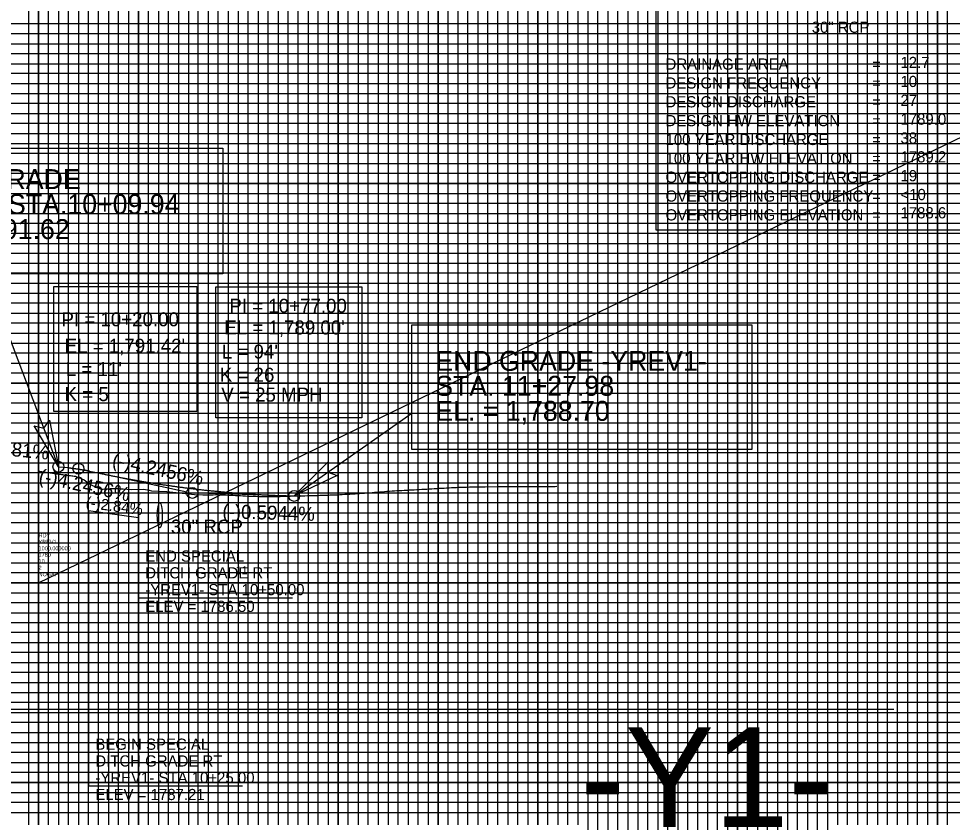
# Model space of a CAD drawing. Extents: x 572269 to 579912, y -56875 to -49627.
# Drawn here: x 574574.7 to 575042.2, y -53465.2 to -53065.2 of the extents above; entities that cross this region are included whole.
import ezdxf

# ---------------------------------------------------------------- set-up
doc = ezdxf.new("R2010")
doc.units = 0
for name, color, linetype in [('Default', 7, 'Continuous'), ('Exist Profile Cell', 7, 'Continuous'), ('Exist Vertical Profile Ground Line', 7, 'Continuous'), ('Prop Grid Mask', 7, 'Continuous'), ('Prop PFL Structure Hydraulic Data Label CELL', 7, 'Continuous'), ('Prop PFL Text', 7, 'Continuous'), ('Prop Vertical Profile Ditch Grade Right', 7, 'Continuous'), ('Prop Vertical Profile Ditch Grade Right Label', 7, 'Continuous'), ('Prop Vertical Profile Grade', 7, 'Continuous'), ('Prop Vertical Profile Grade Label', 7, 'Continuous'), ('Prop VPI Label', 7, 'Continuous'), ('Scratch_Level_0', 7, 'Continuous'), ('Scratch_Level_3', 7, 'Continuous'), ('Scratch_Level_5', 7, 'Continuous'), ('Scratch_Level_6', 7, 'Continuous'), ('Sheet Cutting Line CELL', 7, 'Continuous'), ('Sheet DOT Grid CELL', 7, 'Continuous'), ('Sheet Profile Grid Major CELL', 7, 'Continuous'), ('Sheet Profile Grid Middle CELL', 7, 'Continuous'), ('Sheet Profile Grid Minor CELL', 7, 'Continuous'), ('Typical Terminator CELL', 7, 'Continuous')]:
    doc.layers.add(name, color=color, linetype=linetype)

# ---------------------------------------------------------------- blocks, each defined once
blk = doc.blocks.new('TERMINATOR')
at = {"layer": 'Typical Terminator CELL'}
blk.add_lwpolyline([(-0.4687, 0.0807), (0, 0), (-0.4713, -0.0833), (-0.4114, 0)], close=True, dxfattribs=at)
blk = doc.blocks.new('PROFILE SHEET SINGLE')
at = {"layer": 'Sheet DOT Grid CELL'}
for p, q in [((15, 21), (15, 0.5)), ((16, 21), (16, 0.5)), ((17, 21), (17, 0.5)), ((18, 21), (18, 0.5)), ((19, 21), (19, 0.5)), ((20, 21), (20, 0.5)), ((21, 21), (21, 0.5)), ((22, 21), (22, 0.5)), ((23, 21), (23, 0.5)), ((24, 21), (24, 0.5)), ((0, 14.5), (30, 14.5)), ((0, 13.5), (30, 13.5)), ((0, 12.5), (30, 12.5)), ((0, 11.5), (30, 11.5)), ((0, 10.5), (30, 10.5)), ((0, 9.5), (30, 9.5)), ((0, 8.5), (30, 8.5)), ((0, 7.5), (30, 7.5))]:
    blk.add_line(p, q, dxfattribs=at)
at = {"layer": 'Sheet Profile Grid Major CELL'}
for points in [[(15, 21), (15, 0.5), (16, 0.5), (16, 21)], [(17, 21), (17, 0.5), (18, 0.5), (18, 21)], [(19, 21), (19, 0.5), (20, 0.5), (20, 21)], [(21, 21), (21, 0.5), (22, 0.5), (22, 21)], [(23, 21), (23, 0.5), (24, 0.5), (24, 21)], [(30, 13.5), (0, 13.5), (0, 14.5), (30, 14.5)], [(30, 11.5), (0, 11.5), (0, 12.5), (30, 12.5)], [(30, 9.5), (0, 9.5), (0, 10.5), (30, 10.5)], [(30, 7.5), (0, 7.5), (0, 8.5), (30, 8.5)]]:
    blk.add_lwpolyline(points, dxfattribs=at)
at = {"layer": 'Sheet Profile Grid Middle CELL'}
for points in [[(14.5, 21), (14.5, 0.5), (15.5, 0.5), (15.5, 21)], [(16.5, 21), (16.5, 0.5), (17.5, 0.5), (17.5, 21)], [(18.5, 21), (18.5, 0.5), (19.5, 0.5), (19.5, 21)], [(20.5, 21), (20.5, 0.5), (21.5, 0.5), (21.5, 21)], [(22.5, 21), (22.5, 0.5), (23.5, 0.5), (23.5, 21)], [(30, 15), (0, 15), (0, 14), (30, 14)], [(30, 13), (0, 13), (0, 12), (30, 12)], [(30, 11), (0, 11), (0, 10), (30, 10)], [(30, 9), (0, 9), (0, 8), (30, 8)]]:
    blk.add_lwpolyline(points, dxfattribs=at)
at = {"layer": 'Sheet Profile Grid Minor CELL'}
for points in [[(14.9, 21), (14.9, 0.5), (15.1, 0.5), (15.1, 21)], [(15.2, 21), (15.2, 0.5)], [(15.2, 0.5), (15.3, 0.5), (15.3, 20.988)], [(15.4, 20.988), (15.4, 0.5), (15.6, 0.5), (15.6, 21)], [(15.7, 21), (15.7, 0.5), (15.8, 0.5), (15.8, 21)], [(15.9, 21), (15.9, 0.5), (16.1, 0.5), (16.1, 21)], [(16.2, 21), (16.2, 0.5), (16.3, 0.5), (16.3, 21)], [(16.4, 21), (16.4, 0.5), (16.6, 0.5), (16.6, 21)], [(16.7, 21), (16.7, 0.5), (16.8, 0.5), (16.8, 21)], [(16.9, 21), (16.9, 0.5), (17.1, 0.5), (17.1, 21)], [(17.2, 21), (17.2, 0.5), (17.3, 0.5), (17.3, 21)], [(17.4, 21), (17.4, 0.5), (17.6, 0.5), (17.6, 21)], [(17.7, 21), (17.7, 0.5), (17.8, 0.5), (17.8, 21)], [(17.9, 21), (17.9, 0.5), (18.1, 0.5), (18.1, 21)], [(18.2, 21), (18.2, 0.5), (18.3, 0.5), (18.3, 21)], [(18.4, 21), (18.4, 0.5), (18.6, 0.5), (18.6, 21)], [(18.7, 21), (18.7, 0.5), (18.8, 0.5), (18.8, 21)], [(18.9, 21), (18.9, 0.5), (19.1, 0.5), (19.1, 21)], [(19.2, 21), (19.2, 0.5), (19.3, 0.5), (19.3, 21)], [(19.4, 21), (19.4, 0.5), (19.6, 0.5), (19.6, 21)], [(19.7, 21), (19.7, 0.5), (19.8, 0.5), (19.8, 21)], [(19.9, 21), (19.9, 0.5), (20.1, 0.5), (20.1, 21)], [(20.2, 21), (20.2, 0.5), (20.3, 0.5), (20.3, 21)], [(20.4, 21), (20.4, 0.5), (20.6, 0.5), (20.6, 21)], [(20.7, 21), (20.7, 0.5), (20.8, 0.5), (20.8, 21)], [(20.9, 21), (20.9, 0.5), (21.1, 0.5), (21.1, 21)], [(21.2, 21), (21.2, 0.5), (21.3, 0.5), (21.3, 21)], [(21.4, 21), (21.4, 0.5)], [(21.4, 0.5), (21.6, 0.5), (21.6, 21)], [(21.7, 21), (21.7, 0.5), (21.8, 0.5), (21.8, 21)], [(21.9, 21), (21.9, 0.5), (22.1, 0.5), (22.1, 21)], [(22.2, 21), (22.2, 0.5), (22.3, 0.5), (22.3, 21)], [(22.4, 21), (22.4, 0.5), (22.6, 0.5), (22.6, 21)], [(22.7, 21), (22.7, 0.5), (22.8, 0.5), (22.8, 21)], [(22.9, 21), (22.9, 0.5), (23.1, 0.5), (23.1, 21)], [(23.2, 21), (23.2, 0.5), (23.3, 0.5), (23.3, 21)], [(23.4, 21), (23.4, 0.5), (23.6, 0.5), (23.6, 21)], [(23.7, 21), (23.7, 0.5), (23.8, 0.5), (23.8, 21)], [(23.9, 21), (23.9, 0.5), (24.1, 0.5), (24.1, 21)], [(29, 15.1), (1, 15.1), (1, 14.9), (29, 14.9)], [(29, 14.8), (1, 14.8), (1, 14.7), (29, 14.7)], [(29, 14.6), (1, 14.6), (1, 14.4), (29, 14.4)], [(29, 14.3), (1, 14.3), (1, 14.2), (29, 14.2)], [(29, 14.1), (1, 14.1), (1, 13.9), (29, 13.9)], [(29, 13.8), (1, 13.8), (1, 13.7), (29, 13.7)], [(29, 13.6), (1, 13.6), (1, 13.4), (29, 13.4)], [(29, 13.3), (1, 13.3), (1, 13.2), (29, 13.2)], [(29, 13.1), (1, 13.1), (1, 12.9), (29, 12.9)], [(29, 12.8), (1, 12.8), (1, 12.7), (29, 12.7)], [(29, 12.6), (1, 12.6), (1, 12.4), (29, 12.4)], [(29, 12.3), (1, 12.3), (1, 12.2), (29, 12.2)], [(29, 12.1), (1, 12.1), (1, 11.9), (29, 11.9)], [(29, 11.8), (1, 11.8), (1, 11.7), (29, 11.7)], [(29, 11.6), (1, 11.6), (1, 11.4), (29, 11.4)], [(29, 11.3), (1, 11.3), (1, 11.2), (29, 11.2)], [(29, 11.1), (1, 11.1), (1, 10.9), (29, 10.9)], [(29, 10.8), (1, 10.8), (1, 10.7), (29, 10.7)], [(29, 10.6), (1, 10.6)], [(1, 10.4), (29, 10.4)], [(29, 10.3), (1, 10.3), (1, 10.2), (29, 10.2)], [(29, 10.1), (1, 10.1), (1, 9.9), (29, 9.9)], [(29, 9.8), (1, 9.8), (1, 9.7), (29, 9.7)], [(29, 9.6), (1, 9.6), (1, 9.4), (29, 9.4)], [(29, 9.3), (1, 9.3), (1, 9.2), (29, 9.2)], [(29, 9.1), (1, 9.1), (1, 8.9), (29, 8.9)], [(29, 8.8), (1, 8.8), (1, 8.7), (29, 8.7)], [(29, 8.6), (1, 8.6), (1, 8.4), (29, 8.4)], [(29, 8.3), (1, 8.3), (1, 8.2), (29, 8.2)], [(29, 8.1), (1, 8.1), (1, 7.9), (29, 7.9)], [(29, 7.8), (1, 7.8), (1, 7.7), (29, 7.7)], [(29, 7.6), (1, 7.6), (1, 7.4), (29, 7.4)], [(29, 7.3), (1, 7.3), (1, 7.2), (29, 7.2)]]:
    blk.add_lwpolyline(points, dxfattribs=at)

msp = doc.modelspace()

# ---------------------------------------------------------------- linework, layer by layer
at = {"layer": 'Default'}
msp.add_ellipse((574645.39, -53313.96), major_axis=(0, 6.25), ratio=0.2, dxfattribs=at)
at = {"layer": 'Exist Profile Cell'}
for q in [(574584.69, -53097.71), (574844.14, -53347.71), (574584.69, -53597.71)]:
    msp.add_line((574584.69, -53347.71), q, dxfattribs=at)
at = {"layer": 'Exist Vertical Profile Ground Line'}
msp.add_lwpolyline([(574584.69, -53291.74), (574585.28, -53291.76), (574593.74, -53293.1), (574594.37, -53293.2), (574595, -53293.29), (574595.63, -53293.39), (574596.26, -53293.48), (574596.89, -53293.57), (574597.52, -53293.65), (574598.15, -53293.74), (574598.77, -53293.82), (574599.4, -53293.9), (574600.03, -53293.97), (574600.66, -53294.05), (574601.29, -53294.12), (574601.92, -53294.19), (574602.55, -53294.25), (574603.18, -53294.37), (574603.81, -53294.62), (574604.43, -53294.87), (574605.06, -53295.12), (574605.69, -53295.36), (574606.32, -53295.6), (574607.15, -53295.92), (574607.58, -53296.22), (574608.21, -53296.66), (574608.84, -53297.09), (574609.47, -53297.51), (574610.09, -53297.93), (574610.72, -53298.42), (574611.35, -53298.82), (574611.98, -53299.09), (574612.61, -53299.36), (574613.24, -53299.63), (574613.87, -53299.94), (574614.5, -53300.24), (574615.13, -53300.53), (574615.97, -53300.91), (574616.38, -53300.87), (574617.01, -53300.81), (574617.64, -53300.74), (574618.38, -53300.65), (574618.9, -53300.64), (574619.53, -53300.62), (574620.16, -53300.6), (574620.79, -53300.57), (574621.41, -53300.54), (574622.04, -53300.51), (574622.67, -53300.46), (574623.3, -53300.45), (574623.93, -53300.51), (574624.56, -53300.56), (574625.19, -53300.6), (574625.82, -53300.65), (574626.45, -53300.69), (574627.07, -53300.72), (574631.04, -53300.94), (574637.48, -53300.88), (574640.1, -53301.32), (574641.2, -53301.65), (574648.86, -53301.92), (574662.7, -53303.51), (574666.93, -53303.64), (574672.09, -53303.59), (574673.34, -53303.58), (574674.62, -53303.57), (574675.82, -53303.62), (574677.07, -53303.68), (574678.31, -53303.73), (574679.55, -53303.79), (574680.8, -53303.85), (574682.04, -53303.9), (574683.28, -53303.96), (574684.53, -53304.02), (574685.77, -53304.08), (574687.01, -53304.15), (574688.26, -53304.21), (574689.5, -53304.27), (574690.74, -53304.34), (574691.43, -53304.38), (574691.99, -53304.39), (574693.23, -53304.41), (574694.47, -53304.44), (574695.72, -53304.47), (574696.96, -53304.49), (574698.2, -53304.52), (574699.45, -53304.55), (574700.69, -53304.58), (574700.99, -53304.59), (574701.93, -53304.55), (574703.17, -53304.51), (574704.42, -53304.47), (574705.66, -53304.43), (574706.9, -53304.39), (574708.15, -53304.35), (574709.39, -53304.31), (574710.63, -53304.28), (574711.88, -53304.25), (574713.12, -53304.21), (574714.36, -53304.18), (574715.61, -53304.15), (574716.85, -53304.13), (574718.09, -53304.1), (574719.34, -53304.08), (574720.58, -53304.06), (574721.82, -53304.04), (574723.17, -53304.01), (574724.31, -53303.96), (574725.55, -53303.9), (574726.17, -53303.87), (574726.8, -53303.85), (574728.04, -53303.81), (574729.28, -53303.77), (574730.53, -53303.73), (574731.77, -53303.69), (574733.08, -53303.65), (574734.26, -53303.6), (574735.5, -53303.55), (574735.97, -53303.53), (574736.74, -53303.49), (574737.99, -53303.41), (574739.23, -53303.33), (574740.47, -53303.26), (574741.72, -53303.19), (574743.18, -53303.1), (574744.2, -53303.05), (574745.14, -53303), (574745.45, -53302.98), (574746.69, -53302.88), (574747.93, -53302.79), (574749.18, -53302.7), (574750.42, -53302.61), (574751.66, -53302.51), (574752.91, -53302.41), (574754.15, -53302.31), (574755.39, -53302.21), (574756.64, -53302.11), (574757.88, -53302.01), (574759.13, -53301.91), (574760.36, -53301.81), (574761.81, -53301.7), (574762.85, -53301.64), (574764.09, -53301.57), (574765.34, -53301.51), (574766.58, -53301.44), (574767.82, -53301.37), (574769.07, -53301.31), (574769.64, -53301.28), (574770.31, -53301.23), (574770.87, -53301.19), (574771.55, -53301.15), (574772.8, -53301.09), (574774.04, -53301.02), (574775.28, -53300.95), (574776.53, -53300.89), (574777.77, -53300.82), (574779.01, -53300.76), (574780.26, -53300.69), (574781.66, -53300.62), (574782.74, -53300.55), (574783.99, -53300.47), (574784.47, -53300.44), (574785.23, -53300.39), (574786.47, -53300.33), (574787.72, -53300.26), (574788.96, -53300.19), (574790.2, -53300.13), (574791.45, -53300.06), (574792.69, -53299.99), (574793.16, -53299.97), (574793.93, -53299.95), (574795.18, -53299.91), (574795.71, -53299.9), (574796.42, -53299.87), (574797.66, -53299.82), (574798.91, -53299.76), (574800.45, -53299.7), (574801.39, -53299.7), (574808.28, -53299.67), (574814.47, -53299.54), (574822.76, -53299.5), (574834.06, -53299.44), (574843.4, -53299.42), (574844.14, -53299.41)], dxfattribs=at)
at = {"layer": 'Prop Grid Mask'}
for points in [[(574893.73, -53170.98), (575080.54, -53170.98), (575080.54, -53048.62), (574893.73, -53048.62)], [(574491.18, -53130.09), (574676.93, -53130.09), (574676.93, -53192.94), (574491.18, -53192.94)], [(574592.36, -53199.34), (574663.88, -53199.34), (574663.88, -53261.85), (574592.36, -53261.85)], [(574673.5, -53199.53), (574746.53, -53199.53), (574746.53, -53265.1), (574673.5, -53265.1)], [(574771.52, -53218.49), (574941.8, -53218.49), (574941.8, -53280.94), (574771.52, -53280.94)]]:
    msp.add_lwpolyline(points, close=True, dxfattribs=at)
at = {"layer": 'Prop PFL Text'}
for p, q in [((574594.63, -53289.61), (574558.07, -53192.94)), ((574712.67, -53304.22), (574771.52, -53262.83))]:
    msp.add_line(p, q, dxfattribs=at)
at = {"layer": 'Prop Vertical Profile Ditch Grade Right'}
msp.add_line((574634.69, -53315.21), (574609.69, -53311.66), dxfattribs=at)
at = {"layer": 'Prop Vertical Profile Ditch Grade Right Label'}
for p, q in [((574609.69, -53311.66), (574609.69, -53449.5)), ((574634.69, -53315.21), (574634.69, -53355.28)), ((574634.69, -53355.28), (574711.83, -53355.28)), ((574609.69, -53449.5), (574686.83, -53449.5))]:
    msp.add_line(p, q, dxfattribs=at)
at = {"layer": 'Prop Vertical Profile Grade'}
for p, q in [((574594.63, -53289.61), (574599.17, -53290.06)), ((574610.21, -53291.78), (574614.69, -53292.73)), ((574708.69, -53304.11), (574712.67, -53304.22))]:
    msp.add_line(p, q, dxfattribs=at)
for points in [[(574599.17, -53290.06), (574599.39, -53290.08), (574599.61, -53290.1), (574599.83, -53290.13), (574600.05, -53290.15), (574600.27, -53290.18), (574600.49, -53290.2), (574600.71, -53290.23), (574600.93, -53290.25), (574601.16, -53290.28), (574601.38, -53290.3), (574601.6, -53290.33), (574601.82, -53290.36), (574602.04, -53290.39), (574602.26, -53290.42), (574602.48, -53290.44), (574602.7, -53290.47), (574602.92, -53290.5), (574603.14, -53290.54), (574603.36, -53290.57), (574603.58, -53290.6), (574603.8, -53290.63), (574604.03, -53290.66), (574604.25, -53290.7), (574604.47, -53290.73), (574604.69, -53290.76), (574604.91, -53290.8), (574605.13, -53290.83), (574605.35, -53290.87), (574605.57, -53290.91), (574605.79, -53290.94), (574606.01, -53290.98), (574606.23, -53291.02), (574606.45, -53291.06), (574606.67, -53291.09), (574606.9, -53291.13), (574607.12, -53291.17), (574607.34, -53291.21), (574607.56, -53291.25), (574607.78, -53291.29), (574608, -53291.34), (574608.22, -53291.38), (574608.44, -53291.42), (574608.66, -53291.46), (574608.88, -53291.51), (574609.1, -53291.55), (574609.32, -53291.6), (574609.54, -53291.64), (574609.76, -53291.69), (574609.99, -53291.73), (574610.21, -53291.78)], [(574614.69, -53292.73), (574616.57, -53293.13), (574618.45, -53293.52), (574620.33, -53293.9), (574622.21, -53294.27), (574624.09, -53294.64), (574625.97, -53295), (574627.85, -53295.36), (574629.73, -53295.7), (574631.61, -53296.04), (574633.49, -53296.38), (574635.37, -53296.71), (574637.25, -53297.03), (574639.13, -53297.34), (574641.01, -53297.65), (574642.89, -53297.95), (574644.77, -53298.24), (574646.65, -53298.52), (574648.53, -53298.8), (574650.41, -53299.07), (574652.29, -53299.34), (574654.17, -53299.6), (574656.05, -53299.85), (574657.93, -53300.09), (574659.81, -53300.33), (574661.69, -53300.56), (574663.57, -53300.79), (574665.45, -53301), (574667.33, -53301.21), (574669.21, -53301.42), (574671.09, -53301.61), (574672.97, -53301.8), (574674.85, -53301.99), (574676.73, -53302.16), (574678.61, -53302.33), (574680.49, -53302.49), (574682.37, -53302.65), (574684.25, -53302.8), (574686.13, -53302.94), (574688.01, -53303.08), (574689.89, -53303.2), (574691.77, -53303.32), (574693.65, -53303.44), (574695.53, -53303.55), (574697.41, -53303.65), (574699.29, -53303.74), (574701.17, -53303.83), (574703.05, -53303.91), (574704.93, -53303.98), (574706.81, -53304.05), (574708.69, -53304.11)]]:
    msp.add_spline(points, degree=3, dxfattribs=at)
at = {"layer": 'Prop VPI Label'}
for p, q in [((574599.17, -53290.06), (574601.95, -53290.34)), ((574610.21, -53291.78), (574607.38, -53291.18)), ((574614.69, -53292.73), (574659, -53302.14)), ((574708.69, -53304.11), (574664.44, -53302.79))]:
    msp.add_line(p, q, dxfattribs=at)
for centre in [(574594.63, -53289.61), (574604.69, -53290.61), (574661.69, -53302.71), (574712.67, -53304.22)]:
    msp.add_circle(centre, 2.75, dxfattribs=at)
at = {"layer": 'Scratch_Level_0'}
msp.add_line((575012.91, -53411.24), (573884.69, -53411.24), dxfattribs=at)
at = {"layer": 'Scratch_Level_3'}
msp.add_line((574584.69, -56875.35), (574584.69, -49627.25), dxfattribs=at)
at = {"layer": 'Scratch_Level_5'}
msp.add_line((574784.69, -53797.71), (574784.69, -52363.21), dxfattribs=at)
at = {"layer": 'Scratch_Level_6'}
for p, q in [((574584.69, -54007.71), (574584.69, -52269.82)), ((574584.69, -53347.71), (576235.41, -52550.12)), ((576826.8, -53347.71), (572993.85, -53347.71))]:
    msp.add_line(p, q, dxfattribs=at)

# ---------------------------------------------------------------- block references
at = {"layer": 'Prop PFL Text'}
for p, xscale, yscale, rotation in [((574594.63, -53289.61), 50.00000000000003, 50.000000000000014, -69.33663760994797), ((574712.67, -53304.22), 50.000000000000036, 50.00000000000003, -144.8852438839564)]:
    msp.add_blockref('TERMINATOR', p, dxfattribs=dict(at, xscale=xscale, yscale=yscale, rotation=rotation))
at = {"layer": 'Sheet Cutting Line CELL', "xscale": 50, "yscale": 50}
msp.add_blockref('PROFILE SHEET SINGLE', (573834.69, -53822.71), dxfattribs=at)

# ---------------------------------------------------------------- texts
at = {"layer": 'Default'}
for s, height, p in [('30" RCP', 7, (574650.92, -53323.1)), ('11', 4, (574683.36, -53343.46))]:
    msp.add_text(s, height=height, dxfattribs=at).set_placement(p)
at = {"layer": 'Exist Profile Cell'}
for s, p in [('RDY', (574584.69, -53324.96)), ('YREV1', (574584.69, -53328.21)), ('1000.000000', (574584.69, -53331.46)), ('1780', (574584.69, -53334.71)), ('2', (574584.69, -53341.21)), ('10', (574584.69, -53337.96)), ('NOGAP', (574584.69, -53344.46))]:
    msp.add_text(s, height=2, dxfattribs=at).set_placement(p)
at = {"layer": 'Prop PFL Structure Hydraulic Data Label CELL'}
for s, height, p in [('30" RCP', 5.6, (574971.79, -53072.26)), ('DRAINAGE AREA', 5.5999, (574898.61, -53090.72)), ('= ', 5.6, (575002.03, -53090.72)), ('12.7', 5.6, (575016.22, -53089.89)), ('DESIGN FREQUENCY', 5.5999, (574898.61, -53100.16)), ('= ', 5.6, (575002.03, -53100.16)), ('10', 5.6, (575016.22, -53099.41)), ('DESIGN DISCHARGE', 5.5999, (574898.61, -53109.6)), ('= ', 5.6, (575002.03, -53109.6)), ('27', 5.6, (575016.22, -53108.85)), ('DESIGN HW ELEVATION', 5.5999, (574898.61, -53119.04)), ('= ', 5.6, (575002.03, -53119.04)), ('1789.0', 5.6, (575016.22, -53118.29)), ('100 YEAR DISCHARGE', 5.5999, (574898.61, -53128.48)), ('= ', 5.6, (575002.03, -53128.48)), ('38', 5.6, (575016.22, -53127.73)), ('100 YEAR HW ELEVATION', 5.5999, (574898.61, -53137.92)), ('= ', 5.6, (575002.03, -53137.92)), ('1789.2', 5.6, (575016.22, -53137.17)), ('OVERTOPPING DISCHARGE', 5.5999, (574898.61, -53147.36)), ('= ', 5.6, (575002.03, -53147.36)), ('19', 5.6, (575016.22, -53146.61)), ('OVERTOPPING FREQUENCY', 5.5999, (574898.61, -53156.8)), ('=', 5.6, (575002.03, -53156.8)), ('<10', 5.6, (575016.22, -53156.05)), ('OVERTOPPING ELEVATION', 5.5999, (574898.61, -53166.24)), ('= ', 5.6, (575002.03, -53166.24)), ('1788.6', 5.6, (575016.22, -53165.2))]:
    msp.add_text(s, height=height, rotation=360, dxfattribs=at).set_placement(p)
at = {"layer": 'Prop PFL Text'}
for s, height, p in [('BEGIN GRADE', 10, (574512.92, -53150.54)), ('-YREV1- STA.10+09.94', 10, (574512.92, -53163.06)), ('EL. = 1,791.62', 10, (574512.92, -53175.58)), ('END GRADE -YREV1- ', 10, (574783.29, -53241.56)), ('STA. 11+27.98', 10, (574783.29, -53254.08)), ('EL. = 1,788.70', 10, (574783.29, -53266.6)), ('-Y1-', 50, (574856.05, -53470.07))]:
    msp.add_text(s, height=height, dxfattribs=at).set_placement(p)
at = {"layer": 'Prop Vertical Profile Ditch Grade Right'}
msp.add_text('(-)2.84%', height=5.6, rotation=352.2836, dxfattribs=at).set_placement((574608.08, -53310.04))
at = {"layer": 'Prop Vertical Profile Ditch Grade Right Label'}
for s, p in [('END SPECIAL', (574638.12, -53337.14)), ('DITCH GRADE RT', (574638.12, -53345.54)), ('-YREV1- STA 10+50.00', (574638.12, -53353.94)), ('ELEV = 1786.50', (574638.12, -53362.34)), ('BEGIN SPECIAL', (574613.12, -53431.36)), ('DITCH GRADE RT', (574613.12, -53439.76)), ('-YREV1- STA 10+25.00', (574613.12, -53448.16)), ('ELEV = 1787.21', (574613.12, -53456.56))]:
    msp.add_text(s, height=5.6, dxfattribs=at).set_placement(p)
at = {"layer": 'Prop Vertical Profile Grade Label'}
for s, rotation, p in [('(-)1.9881%', 354.3232, (574543.52, -53281.51)), ('(-)4.2456%', 348.0151, (574621.13, -53289.31)), ('(-)4.2456%', 348.0151, (574584.41, -53297.44)), ('(-)0.5944%', 358.2978, (574676.64, -53315.38))]:
    msp.add_text(s, height=7, rotation=rotation, dxfattribs=at).set_placement(p)
at = {"layer": 'Prop VPI Label'}
for s, p in [('PI = 10+77.00', (574680.23, -53212.46)), ('PI = 10+20.00', (574596.16, -53219.26)), ("EL = 1,789.00'", (574677.66, -53223.34)), ("EL = 1,791.42'", (574597.73, -53232.49)), ("L = 94'", (574676.47, -53235.41)), ("L = 11'", (574598.37, -53244.17)), ('K = 26', (574675.44, -53247.01)), ('K = 5', (574597.73, -53256.73)), ('V = 25 MPH', (574676.18, -53256.97))]:
    msp.add_text(s, height=7, dxfattribs=at).set_placement(p)

doc.saveas('drawing.dxf')
